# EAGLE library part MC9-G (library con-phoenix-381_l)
Mini-Combicon 3.81mm horizontal 9-polig (mit Gegenstecker)
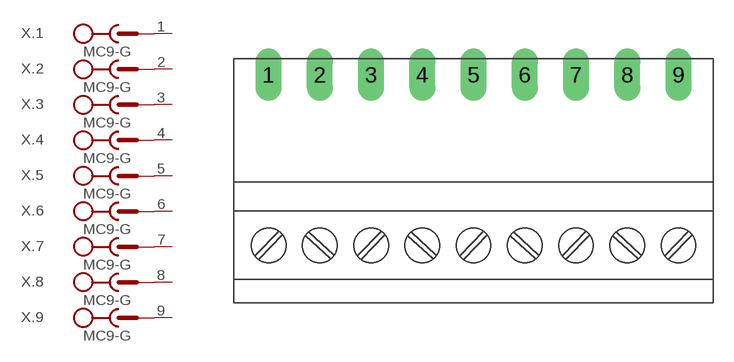
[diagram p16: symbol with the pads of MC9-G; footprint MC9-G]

Designator prefix X; gates .1=SK+V .2=SK+V .3=SK+V .4=SK+V .5=SK+V .6=SK+V .7=SK+V .8=SK+V .9=SK+V

## MC9-G  [MC9-G]
1  .1:SK  pas
2  .2:SK  pas
3  .3:SK  pas
4  .4:SK  pas
5  .5:SK  pas
6  .6:SK  pas
7  .7:SK  pas
8  .8:SK  pas
9  .9:SK  pas

## Footprint MC9-G (pad centres in mm)
Mini-Combicon 3.81mm horizontal 9-polig (mit Gegenstecker)
drill 1.3 long: 1 -15.24,0; 2 -11.43,0; 3 -7.62,0; 4 -3.81,0; 5 0,0; 6 3.81,0; 7 7.62,0; 8 11.43,0; 9 15.24,0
